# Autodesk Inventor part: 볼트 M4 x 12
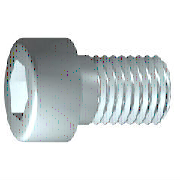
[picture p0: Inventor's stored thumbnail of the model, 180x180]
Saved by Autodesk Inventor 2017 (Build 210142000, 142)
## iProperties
IsCustomPart: 0
Created: 2016-05
Part Number: 볼트 M4 x 12
Material: 강, 연강
Description: 6각머리 태핑 나사
Document SubType Name: Modeling
Standard: KS B 1003
Designer: mduedu
Standards Organization: KS
Language: ko-KR
Size Designation: M 4 x 12
Categories: <MemberInstance><Categories><Category DisplayName="조임쇠" InternalName="e4da775c-781d-43d5-af7c-5136215cf5a6" Mnemonic="FSTN"><Category DisplayName="볼트" InternalN
Density: 1 g/cm^3
Appearance: 연마 - 진회색
Author: mduedu
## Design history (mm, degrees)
sketch "스케치1"
  geometry: L1 (-1, 0)-(12, 0); L2 (12, 0)-(12, 2); L3 (12, 2)-(1.75, 2); L4 (1.75, 2)-(1.32, 2); L5 (1.32, 2)-(0, 2); L6 (0, 2)-(0, 3.5); L7 (0, 3.5)-(-4, 3.5); L8 (-4, 3.5)-(-4, 1.732); L9 (-4, 1.732)-(-2, 1.732); L10 (-2, 1.732)-(-1, 0); L11 (-7.2, 0)-(15.2, 0) reference; L12 (0, -0.7)-(0, 4.2) reference; L13 (1.75, 2)-(0, 2)
  constraints: 22 end point, 6 parallel, 2 collinear, 2 perpendicular, 1 horizontal, 1 point on line
  dimensions: "d1" = 10.25 distance from line of L3.end L2 (= GEL); "d2" = 0.42952 distance of L4.end L3.end (computed from GAL); "d3" = 4 distance between parallel lines of L8 L6 (= KOH); "d4" = 2 distance of L8.end L9.end (= INTI); "d5" = 60 deg angle of L10 L1; "d6" = 4 diameter of L3 L1 (= GD); "d7" = 4 diameter of L5 L1 (= BDM); "d8" = 3.4641 diameter of L9 L1 (= 1.1547 x SW); "d9" = 7 diameter of L7 L1 (= KOD); "d26" = 12 distance between parallel lines of L12 L2 (= NLG)
revolve "본체" sketch "스케치1" stored, may be unused: angle "d10" = 90 deg
sketch "스케치2"
  geometry: L1 (0, -4.9)-(0, 4.9) reference; L2 (-4.9, 0)-(4.9, 0) reference; L3 (1.732, 0)-(0.866, -1.5); L4 (0.866, -1.5)-(-0.866, -1.5); L5 (-0.866, -1.5)-(-1.732, 0); L6 (-1.732, 0)-(-0.866, 1.5); L7 (-0.866, 1.5)-(0.866, 1.5); L8 (0.866, 1.5)-(1.732, 0); 2 further points
  constraints: 12 end point, 1 coincident, 1 horizontal alignment, 1 point on line, 12 other
extrude "슬롯" join sketch "스케치2" stored distance "d11" = 10; taper "d12" = 0 deg
workplane "Work Plane1"
fillet "Fillet2" dims "d30" = 0.1 (= R)
body "Solid1"
fillet "모깎기1" dims "d17" = 0.4 (= RR)
feature "스레드" dims "d13" = 10.25 (= GEL), "d14" = 0
chamfer "모따기1" distance "d15" = 0.42941 (= -0.5 x SPD + 0.5 x GD); stored, may be unused: second distance "d16" = 0.42941 (= GUL), angle "d27" = 45 deg
other parameters: "GD" = 4 (= NND) [user parameter; used in 2 equation terms], "NLG" = 12 [user parameter; used in 1 equation term], "GEL" = 10.25 [user parameter; used in 2 equation terms], "KOD" = 7 [user parameter; used in 1 equation term], "KOH" = 4 [user parameter; used in 1 equation term], "INTI" = 2 [user parameter; used in 1 equation term], "GAL" = 0.42941 (= 0.61345 x PTC) [user parameter; used in 1 equation term], "GUL" = 0.42941 (= 0.61345 x PTC) [user parameter; used in 1 equation term], "BDM" = 4 (= NND) [user parameter; used in 1 equation term], "SW" = 3 [user parameter; used in 2 equation terms], "RR" = 0.4 [user parameter; used in 1 equation term], "SPD" = 3.14117 (= NND - 1.2269 x PTC) [user parameter; used in 1 equation term], "d19" = 0, "d28" = 0, "d29" = 0, "R" = 0.1 [user parameter; used in 1 equation term], "PHH" = 0.2 [user parameter], "GD1" = 3.14117 (= THREADDIA - 1.2269 x PTC) [user parameter], "THREADDIA" = 4 [user parameter; used in 1 equation term], "FAWI" = 45 deg [user parameter], "TPU" = 14.28571 (computed from PTC) [user parameter], "PTC" = 0.7 [user parameter; used in 5 equation terms], "NND" = 4 [user parameter; used in 3 equation terms], "TOA" = 30 deg [user parameter], "E0" = 3.465 (= 1.155 x SW) [user parameter]
